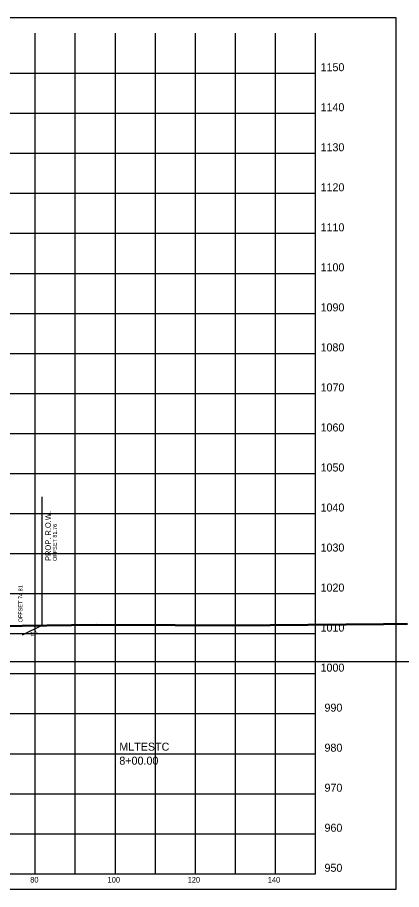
# Model space of a CAD drawing. Extents: x 1131015 to 1136271, y 133453 to 174329.
# Drawn here: x 1131416 to 1131511.9, y 157610.7 to 157828.6 of the extents above; entities that cross this region are included whole.
import ezdxf

# ---------------------------------------------------------------- set-up
doc = ezdxf.new("R2010")
doc.units = 0
for name, color, linetype in [('DESIGN - ROW - Right-of-Way and Easement Labels', 7, 'Continuous'), ('DESIGN - ROW - Right-of-Way Linework', 7, 'Continuous'), ('DESIGN - SCRATCH - User 1', 7, 'Continuous'), ('DESIGN - SHEET - Corner Text', 7, 'Continuous'), ('DESIGN - SHEET - Light Grid', 7, 'Continuous'), ('DESIGN - SHEET - Linework', 7, 'Continuous'), ('DESIGN - SHEET - Plot Shape', 7, 'Continuous'), ('DESIGN - TYPICAL - Slope Tie Text', 7, 'Continuous'), ('DESIGN - TYPICAL - Warning Text', 7, 'Continuous'), ('SURVEY - GROUND - Bottom of Topsoil Layer', 7, 'Continuous'), ('SURVEY - GROUND - Top of Ground', 7, 'Continuous')]:
    doc.layers.add(name, color=color, linetype=linetype)

msp = doc.modelspace()

# ---------------------------------------------------------------- linework, layer by layer
at = {"layer": 'DESIGN - ROW - Right-of-Way Linework'}
msp.add_line((1131422.21, 157676.8), (1131422.21, 157708.8), dxfattribs=at)
at = {"layer": 'DESIGN - SCRATCH - User 1'}
msp.add_line((1131417.27, 157674.33), (1131422.21, 157676.8), dxfattribs=at)
at = {"layer": 'DESIGN - SHEET - Light Grid'}
msp.add_line((1131340.46, 157667.66), (1131640.46, 157667.66), dxfattribs=at)
at = {"layer": 'DESIGN - SHEET - Linework'}
for p, q in [((1131420.46, 157614.66), (1131420.46, 157824.66)), ((1131430.46, 157614.66), (1131430.46, 157824.66)), ((1131440.46, 157614.66), (1131440.46, 157824.66)), ((1131450.46, 157614.66), (1131450.46, 157824.66)), ((1131460.46, 157614.66), (1131460.46, 157824.66)), ((1131470.46, 157614.66), (1131470.46, 157824.66)), ((1131480.46, 157614.66), (1131480.46, 157824.66)), ((1131190.46, 157814.66), (1131490.46, 157814.66)), ((1131190.46, 157804.66), (1131490.46, 157804.66)), ((1131190.46, 157794.66), (1131490.46, 157794.66)), ((1131190.46, 157784.66), (1131490.46, 157784.66)), ((1131190.46, 157774.66), (1131490.46, 157774.66)), ((1131190.46, 157764.66), (1131490.46, 157764.66)), ((1131190.46, 157754.66), (1131490.46, 157754.66)), ((1131190.46, 157744.66), (1131490.46, 157744.66)), ((1131190.46, 157734.66), (1131490.46, 157734.66)), ((1131190.46, 157724.66), (1131490.46, 157724.66)), ((1131190.46, 157714.66), (1131490.46, 157714.66)), ((1131190.46, 157704.66), (1131490.46, 157704.66)), ((1131190.46, 157694.66), (1131490.46, 157694.66)), ((1131190.46, 157684.66), (1131490.46, 157684.66)), ((1131190.46, 157674.66), (1131490.46, 157674.66)), ((1131190.46, 157664.66), (1131490.46, 157664.66)), ((1131190.46, 157654.66), (1131490.46, 157654.66)), ((1131190.46, 157644.66), (1131490.46, 157644.66)), ((1131190.46, 157634.66), (1131490.46, 157634.66)), ((1131190.46, 157624.66), (1131490.46, 157624.66))]:
    msp.add_line(p, q, dxfattribs=at)
msp.add_lwpolyline([(1131190.46, 157824.66), (1131190.46, 157614.66), (1131490.46, 157614.66), (1131490.46, 157824.66)], dxfattribs=at)
at = {"layer": 'DESIGN - SHEET - Plot Shape'}
msp.add_lwpolyline([(1131170.46, 157828.6), (1131510.46, 157828.6), (1131510.46, 157610.72), (1131170.46, 157610.72)], close=True, dxfattribs=at)
at = {"layer": 'SURVEY - GROUND - Bottom of Topsoil Layer'}
for p, q in [((1131396.63, 157676.2), (1131435.7, 157676.74)), ((1131435.7, 157676.74), (1131455.43, 157676.66)), ((1131455.43, 157676.66), (1131469.68, 157676.62)), ((1131469.68, 157676.62), (1131507.41, 157676.92)), ((1131507.41, 157676.92), (1131513.39, 157677.01))]:
    msp.add_line(p, q, dxfattribs=at)
at = {"layer": 'SURVEY - GROUND - Top of Ground'}
for p, q in [((1131396.63, 157676.45), (1131435.7, 157676.99)), ((1131435.7, 157676.99), (1131455.43, 157676.91)), ((1131455.43, 157676.91), (1131469.68, 157676.87)), ((1131469.68, 157676.87), (1131507.41, 157677.17)), ((1131507.41, 157677.17), (1131513.39, 157677.26))]:
    msp.add_line(p, q, dxfattribs=at)

# ---------------------------------------------------------------- texts
at = {"layer": 'DESIGN - ROW - Right-of-Way and Easement Labels'}
for s, height, p in [('PROP. R.O.W.', 1.4, (1131424.36, 157692.8)), ('OFFSET 81.76', 1, (1131425.86, 157692.8))]:
    msp.add_text(s, height=height, rotation=90, dxfattribs=at).set_placement(p)
at = {"layer": 'DESIGN - SCRATCH - User 1'}
msp.add_text('2:1', height=1, rotation=28.1289, dxfattribs=at).set_placement((1131419.5, 157673.93))
at = {"layer": 'DESIGN - SHEET - Corner Text'}
for s, height, p in [('1150', 2, (1131491.7, 157815.16)), ('1140', 2, (1131491.7, 157805.16)), ('1130', 2, (1131491.7, 157795.16)), ('1120', 2, (1131491.7, 157785.16)), ('1110', 2, (1131491.7, 157775.16)), ('1100', 2, (1131491.7, 157765.16)), ('1090', 2, (1131491.7, 157755.16)), ('1080', 2, (1131491.7, 157745.16)), ('1070', 2, (1131491.7, 157735.16)), ('1060', 2, (1131491.7, 157725.16)), ('1050', 2, (1131491.7, 157715.16)), ('1040', 2, (1131491.7, 157705.16)), ('1030', 2, (1131491.7, 157695.16)), ('1020', 2, (1131491.7, 157685.16)), ('1010', 2, (1131491.7, 157675.16)), ('1000', 2, (1131491.7, 157665.16)), ('990', 2, (1131492.68, 157655.16)), ('980', 2, (1131492.68, 157645.16)), ('970', 2, (1131492.68, 157635.16)), ('960', 2, (1131492.68, 157625.16)), ('950', 2, (1131492.68, 157615.16)), ('80', 1.4, (1131419.19, 157612.46)), ('100', 1.4, (1131438.51, 157612.46)), ('120', 1.4, (1131458.51, 157612.46)), ('140', 1.4, (1131478.51, 157612.46))]:
    msp.add_text(s, height=height, dxfattribs=at).set_placement(p)
at = {"layer": 'DESIGN - TYPICAL - Slope Tie Text'}
msp.add_text('OFFSET 74.81', height=1, rotation=90, dxfattribs=at).set_placement((1131417.27, 157677.46))
at = {"layer": 'DESIGN - TYPICAL - Warning Text'}
for s, p in [('MLTESTC', (1131441.46, 157645.41)), ('8+00.00', (1131441.46, 157641.91))]:
    msp.add_text(s, height=2, dxfattribs=at).set_placement(p)

doc.saveas('drawing.dxf')
